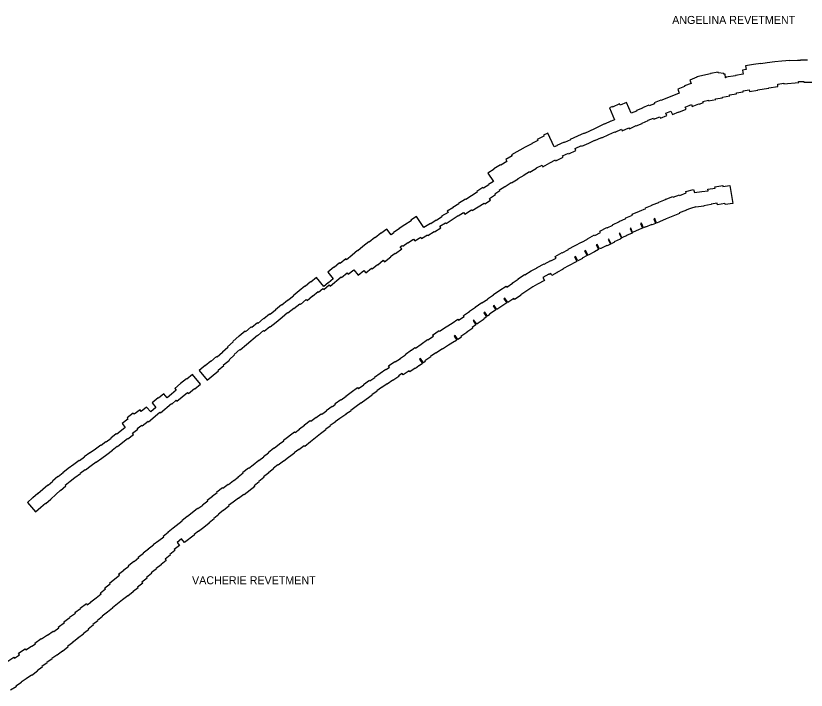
# Model space of a CAD drawing. Extents: x 2650582 to 3923188, y 277893 to 989177.
# Drawn here: x 3479786 to 3495593, y 553438 to 566923 of the extents above; entities that cross this region are included whole.
import ezdxf

# ---------------------------------------------------------------- set-up
doc = ezdxf.new("R2010")
doc.units = 0
doc.layers.add('Level 3', color=7, linetype='Continuous')

msp = doc.modelspace()

# ---------------------------------------------------------------- linework, layer by layer
at = {"layer": 'Level 3'}
for points in [[(3495619, 566037), (3495479, 566039), (3495479, 566026), (3495417, 566027), (3495417, 566031), (3495267, 566023), (3495267, 566030), (3495108, 566015), (3495108, 566018), (3494968, 566000), (3494968, 566004), (3494814, 565984), (3494814, 565982), (3494684, 565962), (3494683, 565967), (3494538, 565949), (3494538, 565952), (3494380, 565925), (3494393, 565848), (3494318, 565835), (3494331, 565754), (3494180, 565728), (3494180, 565724), (3493988, 565694), (3493989, 565685), (3493982, 565684), (3493970, 565758), (3493945, 565754), (3493947, 565770), (3493835, 565785), (3493834, 565793), (3493679, 565769), (3493680, 565761), (3493403, 565704), (3493405, 565693), (3493264, 565639), (3493290, 565571), (3493156, 565520), (3493160, 565508), (3493023, 565455), (3493055, 565374), (3492808, 565273), (3492807, 565275), (3492688, 565231), (3492686, 565235), (3492555, 565183), (3492562, 565163), (3492454, 565122), (3492449, 565133), (3492318, 565080)], [(3492195, 564721), (3492315, 564771), (3492312, 564779), (3492433, 564828), (3492432, 564833), (3492538, 564877), (3492549, 564853), (3492664, 564901), (3492676, 564875), (3492809, 564929), (3492789, 564979), (3492887, 565019), (3492916, 564949), (3493044, 565000), (3493046, 564994), (3493192, 565053), (3493175, 565099), (3493297, 565149), (3493313, 565109), (3493449, 565161), (3493450, 565158), (3493537, 565192), (3493529, 565212), (3493636, 565238), (3493640, 565221), (3493784, 565249), (3493782, 565263), (3493920, 565285), (3493918, 565299), (3494063, 565321), (3494059, 565342), (3494198, 565361), (3494197, 565381), (3494333, 565401), (3494331, 565425), (3494454, 565441), (3494460, 565408), (3494623, 565436), (3494622, 565441), (3494845, 565474), (3494845, 565483), (3495029, 565506), (3495024, 565558), (3495146, 565574), (3495148, 565561), (3495443, 565587), (3495442, 565608), (3495548, 565610), (3495549, 565597), (3495704, 565594)], [(3492095, 564975), (3492001, 565192), (3491870, 565135), (3491859, 565160), (3491721, 565098), (3491717, 565107), (3491658, 565081), (3491761, 564846), (3491690, 564814), (3491689, 564817), (3491559, 564756), (3491557, 564760), (3491358, 564666), (3491359, 564663), (3491156, 564572), (3491155, 564575), (3491022, 564515), (3491020, 564519), (3490875, 564451), (3490879, 564443), (3490758, 564389), (3490755, 564395), (3490604, 564327), (3490606, 564324), (3490552, 564301), (3490423, 564574), (3490338, 564534), (3490347, 564516), (3490214, 564452), (3490223, 564431), (3490103, 564372), (3490107, 564362), (3489973, 564294), (3489971, 564297), (3489700, 564146), (3489712, 564124), (3489584, 564048), (3489605, 564012), (3489487, 563938), (3489481, 563946), (3489346, 563863), (3489350, 563856), (3489229, 563779), (3489337, 563611), (3489239, 563550), (3489243, 563544), (3489137, 563477), (3489129, 563489), (3489005, 563410), (3489015, 563394), (3488786, 563248), (3488779, 563258), (3488642, 563171), (3488644, 563166), (3488524, 563091), (3488528, 563086), (3488415, 563016), (3488430, 562992), (3488302, 562914), (3488309, 562902), (3488196, 562833), (3488194, 562835), (3488083, 562764), (3488077, 562772), (3487943, 562689), (3487801, 562908), (3487685, 562836), (3487693, 562822), (3487566, 562744), (3487568, 562741), (3487451, 562669), (3487456, 562661), (3487342, 562588), (3487347, 562580), (3487292, 562543)], [(3492318, 565080), (3492320, 565074), (3492199, 565026), (3492202, 565019), (3492095, 564975)], [(3487503, 562263), (3487474, 562302), (3487516, 562330), (3487524, 562319), (3487625, 562389), (3487628, 562384), (3487742, 562458), (3487764, 562422), (3487883, 562495), (3487902, 562467), (3488017, 562543), (3488027, 562528), (3488150, 562609), (3488156, 562600), (3488286, 562683), (3488268, 562715), (3488381, 562785), (3488392, 562769), (3488631, 562927), (3488635, 562920), (3488741, 562989), (3488764, 562954), (3488900, 563045), (3488912, 563027), (3489150, 563179), (3489163, 563160), (3489280, 563236), (3489259, 563271), (3489377, 563347), (3489365, 563366), (3489466, 563432), (3489460, 563442), (3489569, 563512), (3489572, 563508), (3489695, 563588), (3489698, 563582), (3489834, 563665), (3489833, 563667), (3489955, 563739), (3489953, 563744), (3490062, 563807), (3490067, 563799), (3490202, 563876), (3490200, 563880), (3490311, 563938), (3490328, 563905), (3490469, 563980), (3490467, 563986), (3490578, 564042), (3490589, 564022), (3490732, 564094), (3490720, 564120), (3490840, 564174), (3490845, 564164), (3490988, 564230), (3490971, 564270), (3491100, 564328), (3491105, 564315), (3491244, 564375), (3491243, 564379), (3491366, 564433), (3491368, 564428), (3491500, 564490), (3491505, 564480), (3491649, 564547), (3491647, 564552), (3491766, 564605), (3491770, 564596), (3491900, 564655), (3491914, 564625), (3492049, 564683), (3492056, 564666), (3492192, 564727), (3492195, 564721)], [(3490711, 562187), (3490712, 562185), (3490836, 562253), (3490834, 562256), (3490973, 562333), (3490975, 562328), (3491102, 562398), (3491104, 562394), (3491221, 562459), (3491218, 562465), (3491359, 562540), (3491364, 562531), (3491477, 562591), (3491465, 562614), (3491608, 562687), (3491611, 562683), (3491726, 562738), (3491722, 562744), (3491856, 562808), (3491855, 562812), (3491988, 562870), (3491984, 562880), (3492121, 562937), (3492114, 562955), (3492262, 563016), (3492262, 563016), (3492385, 563067), (3492378, 563083), (3492514, 563137), (3492513, 563140), (3492647, 563193), (3492646, 563195), (3492777, 563247), (3492775, 563251), (3492924, 563310), (3492931, 563294), (3493061, 563345), (3493067, 563330), (3493195, 563380), (3493188, 563409), (3493341, 563450), (3493357, 563390), (3493504, 563411), (3493505, 563407), (3493632, 563425), (3493627, 563458), (3493773, 563478), (3493769, 563505), (3493926, 563528), (3493929, 563508), (3494069, 563532), (3494129, 563173)], [(3494129, 563173), (3493973, 563147), (3493969, 563167), (3493819, 563145), (3493815, 563174), (3493690, 563157), (3493691, 563147), (3493544, 563126), (3493546, 563117), (3493389, 563095), (3493388, 563100), (3493278, 563071), (3493278, 563073), (3493183, 563035), (3493185, 563032), (3493054, 562981), (3493058, 562971), (3492927, 562919), (3492929, 562915), (3492794, 562862), (3492795, 562860), (3492660, 562806), (3492661, 562803), (3492599, 562779), (3492563, 562868), (3492546, 562862), (3492582, 562772), (3492512, 562744), (3492509, 562751), (3492382, 562698), (3492380, 562701), (3492337, 562683), (3492299, 562775), (3492278, 562767), (3492316, 562675), (3492254, 562649), (3492254, 562649), (3492119, 562593), (3492086, 562674), (3492072, 562669), (3492110, 562578), (3492002, 562531), (3492004, 562528), (3491909, 562482), (3491866, 562574), (3491854, 562568), (3491897, 562477), (3491871, 562464), (3491874, 562458), (3491754, 562401), (3491756, 562398), (3491693, 562366), (3491646, 562457), (3491630, 562449), (3491677, 562357), (3491613, 562325), (3491609, 562333), (3491484, 562267), (3491482, 562272), (3491460, 562261), (3491412, 562351), (3491394, 562341), (3491442, 562251), (3491356, 562205), (3491356, 562206), (3491230, 562136), (3491226, 562142), (3491177, 562230), (3491162, 562222), (3491211, 562133), (3491113, 562079), (3491117, 562073), (3491026, 562023), (3490978, 562111), (3490960, 562101), (3491009, 562013), (3490978, 561997), (3490977, 561999)], [(3487292, 562543), (3487206, 562657), (3487089, 562568), (3487084, 562575), (3486972, 562486), (3486968, 562489), (3486856, 562397), (3486848, 562406), (3486728, 562307), (3486727, 562308), (3486626, 562225), (3486622, 562229), (3486512, 562136), (3486510, 562139), (3486398, 562045), (3486384, 562062), (3486272, 561972), (3486262, 561983), (3486152, 561893), (3486149, 561896), (3486028, 561797), (3486136, 561664), (3486038, 561584), (3486036, 561586), (3485948, 561513), (3485798, 561692), (3485687, 561600), (3485682, 561606), (3485572, 561513), (3485569, 561516), (3485453, 561422), (3485452, 561423), (3485332, 561322), (3485337, 561317), (3485225, 561227), (3485220, 561232), (3485104, 561138), (3485098, 561145), (3484977, 561045)], [(3484618, 560539), (3484625, 560530), (3484741, 560628), (3484753, 560614), (3484867, 560712), (3484875, 560702), (3484990, 560799), (3484994, 560794), (3485112, 560894), (3485110, 560896), (3485221, 560989), (3485228, 560981), (3485344, 561077), (3485349, 561071), (3485463, 561166), (3485477, 561150), (3485592, 561249), (3485610, 561228), (3485717, 561321), (3485721, 561316), (3485832, 561409), (3485842, 561397), (3485929, 561469), (3485947, 561448), (3486054, 561541), (3486076, 561516), (3486292, 561702), (3486301, 561693), (3486412, 561783), (3486436, 561754), (3486545, 561845), (3486636, 561736), (3486748, 561829), (3486788, 561781), (3486901, 561874), (3486911, 561862), (3487019, 561949), (3487023, 561945), (3487132, 562038), (3487160, 562004), (3487284, 562104), (3487282, 562107), (3487370, 562179), (3487377, 562169), (3487503, 562263)], [(3487237, 559927), (3487367, 560013), (3487375, 560001), (3487481, 560072), (3487480, 560074), (3487579, 560143), (3487574, 560150), (3487699, 560242), (3487700, 560240), (3487769, 560291), (3487779, 560279), (3487891, 560359), (3487891, 560359), (3488018, 560450), (3488023, 560442), (3488136, 560520), (3488122, 560540), (3488251, 560630), (3488259, 560619), (3488390, 560704), (3488392, 560701), (3488512, 560780), (3488514, 560777), (3488629, 560855), (3488640, 560839), (3488750, 560913), (3488740, 560927), (3488861, 561009), (3488856, 561016), (3488976, 561097), (3488974, 561100), (3489105, 561188), (3489109, 561182), (3489224, 561259), (3489221, 561263), (3489341, 561344), (3489338, 561349), (3489468, 561436), (3489469, 561434), (3489593, 561518), (3489606, 561499), (3489716, 561574), (3489714, 561576), (3489833, 561656), (3489830, 561661), (3489962, 561748), (3489963, 561746), (3490093, 561824), (3490094, 561823), (3490213, 561886), (3490212, 561889), (3490351, 561963), (3490354, 561958), (3490484, 562027), (3490486, 562023), (3490591, 562078), (3490573, 562111), (3490711, 562187)], [(3490977, 561999), (3490853, 561930), (3490853, 561930), (3490729, 561861), (3490731, 561858), (3490608, 561793), (3490610, 561788), (3490505, 561732), (3490485, 561770), (3490451, 561752), (3490448, 561757), (3490325, 561692), (3490358, 561629), (3490218, 561555), (3490216, 561560), (3490123, 561504), (3490124, 561502), (3490007, 561425), (3490008, 561423), (3489888, 561342), (3489890, 561339), (3489759, 561251), (3489746, 561269), (3489625, 561188), (3489566, 561276), (3489548, 561264), (3489604, 561181), (3489407, 561048), (3489350, 561132), (3489334, 561121), (3489388, 561041), (3489262, 560956), (3489267, 560948), (3489220, 560915), (3489164, 560998), (3489147, 560986), (3489202, 560904), (3489147, 560866), (3489151, 560860), (3489031, 560778), (3489033, 560774), (3489004, 560754), (3488947, 560838), (3488932, 560828), (3488989, 560744), (3488914, 560693), (3488924, 560679), (3488803, 560598), (3488806, 560592), (3488686, 560511), (3488697, 560495), (3488626, 560449), (3488573, 560531), (3488555, 560520), (3488608, 560437), (3488565, 560409), (3488562, 560413), (3488442, 560335), (3488438, 560340), (3488320, 560257), (3488316, 560263), (3488189, 560176), (3488184, 560183), (3488081, 560109), (3488085, 560104), (3487969, 560021), (3487975, 560013), (3487938, 559986), (3487877, 560069), (3487860, 560056), (3487921, 559973), (3487850, 559921), (3487849, 559922), (3487780, 559871), (3487774, 559879), (3487667, 559805), (3487653, 559824), (3487531, 559741), (3487512, 559769), (3487441, 559723)], [(3484977, 561045), (3484980, 561040), (3484871, 560948), (3484861, 560960), (3484746, 560862), (3484741, 560869), (3484626, 560773), (3484617, 560783), (3484506, 560691), (3484496, 560702), (3484380, 560606), (3484372, 560615), (3484255, 560518), (3484252, 560521), (3484126, 560413), (3484136, 560401), (3484019, 560303), (3484029, 560291), (3483918, 560194), (3483922, 560190), (3483812, 560097), (3483801, 560109), (3483687, 560013), (3483683, 560017), (3483575, 559926), (3483571, 559930), (3483452, 559828)], [(3483452, 559828), (3483615, 559634), (3483734, 559734), (3483733, 559735), (3483842, 559825), (3483832, 559838), (3483948, 559932), (3483939, 559943), (3484057, 560040), (3484052, 560046), (3484162, 560142), (3484154, 560152), (3484268, 560249), (3484274, 560242), (3484400, 560348), (3484397, 560350), (3484618, 560539)], [(3486637, 559464), (3486641, 559467), (3486639, 559471), (3486744, 559545), (3486740, 559550), (3486861, 559634), (3486869, 559623), (3486963, 559689), (3486958, 559697), (3487185, 559856), (3487190, 559850), (3487257, 559897), (3487237, 559927)], [(3483480, 559558), (3483319, 559751), (3483204, 559658), (3483198, 559666), (3483082, 559568), (3483081, 559569), (3482963, 559469), (3482990, 559435), (3482899, 559359), (3482901, 559356), (3482812, 559282), (3482744, 559363), (3482640, 559277), (3482636, 559282), (3482516, 559181), (3482589, 559093), (3482483, 559002), (3482399, 559099), (3482295, 559013), (3482272, 559043), (3482155, 558955), (3482135, 558979), (3482011, 558882), (3482028, 558859), (3481912, 558770)], [(3487441, 559723), (3487448, 559713), (3487327, 559628), (3487323, 559635), (3487213, 559558), (3487210, 559563), (3487104, 559488), (3487101, 559493), (3487006, 559427), (3487012, 559418), (3486906, 559344), (3486913, 559334), (3486793, 559250), (3486793, 559251), (3486692, 559180), (3486692, 559181), (3486592, 559111), (3486595, 559108), (3486487, 559032), (3486490, 559027), (3486385, 558954), (3486387, 558952), (3486267, 558868), (3486265, 558869), (3486170, 558803), (3486173, 558798), (3486076, 558730), (3486080, 558724), (3485981, 558649), (3485983, 558647), (3485878, 558567), (3485880, 558564), (3485777, 558486), (3485781, 558482), (3485680, 558405), (3485682, 558402), (3485565, 558313), (3485555, 558327), (3485448, 558245), (3485444, 558252), (3485353, 558183), (3485357, 558178), (3485240, 558089), (3485240, 558090), (3485143, 558016)], [(3482223, 558658), (3482214, 558670), (3482305, 558739), (3482314, 558727), (3482431, 558818), (3482442, 558806), (3482666, 558998), (3482678, 558985), (3482897, 559169), (3482906, 559159), (3482996, 559234), (3483008, 559219), (3483221, 559393), (3483241, 559369), (3483361, 559471), (3483366, 559464), (3483480, 559558)], [(3486182, 559154), (3486173, 559168), (3486289, 559252), (3486293, 559246), (3486391, 559316), (3486388, 559320), (3486494, 559396), (3486493, 559397), (3486620, 559488), (3486637, 559464)], [(3484951, 558279), (3485062, 558364), (3485062, 558363), (3485146, 558427), (3485138, 558437), (3485358, 558605), (3485370, 558590), (3485461, 558659), (3485459, 558662), (3485562, 558740), (3485558, 558744), (3485675, 558833), (3485688, 558817), (3485792, 558897), (3485796, 558891), (3485895, 558967), (3485905, 558954), (3486001, 559022), (3485993, 559032), (3486113, 559116), (3486118, 559109), (3486182, 559154)], [(3481912, 558770), (3481973, 558690), (3481898, 558632), (3481899, 558631), (3481803, 558556), (3481796, 558565), (3481686, 558479), (3481691, 558472), (3481593, 558396), (3481587, 558404), (3481490, 558328), (3481485, 558335), (3481379, 558258), (3481377, 558259), (3481271, 558181), (3481266, 558187), (3481153, 558105), (3481157, 558099), (3481057, 558026), (3481054, 558030), (3480947, 557953), (3480946, 557954), (3480833, 557872), (3480834, 557870), (3480728, 557787), (3480730, 557784), (3480630, 557706), (3480628, 557708), (3480522, 557616), (3480524, 557614), (3480431, 557533), (3480427, 557537), (3480228, 557363), (3480224, 557368), (3480124, 557282), (3480122, 557284), (3480017, 557192)], [(3480017, 557192), (3480180, 557004), (3480286, 557096), (3480284, 557098), (3480378, 557179), (3480383, 557173), (3480483, 557257), (3480589, 557350), (3480586, 557354), (3480679, 557436), (3480682, 557433), (3480787, 557524), (3480775, 557539), (3480872, 557615), (3480871, 557617), (3480965, 557690), (3480966, 557689), (3481079, 557771), (3481074, 557778), (3481175, 557850), (3481178, 557845), (3481292, 557928), (3481291, 557929), (3481391, 558001), (3481396, 557995), (3481509, 558078), (3481507, 558080), (3481606, 558151), (3481607, 558150), (3481717, 558236), (3481715, 558240), (3481813, 558316), (3481817, 558311), (3481927, 558397), (3481925, 558399), (3482021, 558474), (3482027, 558467), (3482137, 558553), (3482119, 558577), (3482223, 558658)], [(3482040, 555931), (3482149, 556016), (3482151, 556014), (3482245, 556088), (3482235, 556101), (3482337, 556179), (3482334, 556182), (3482438, 556263), (3482435, 556267), (3482537, 556346), (3482536, 556348), (3482646, 556433), (3482648, 556431), (3482744, 556506), (3482733, 556520), (3482834, 556598), (3482830, 556602), (3482932, 556682), (3482930, 556685), (3483112, 556827), (3483106, 556834), (3483216, 556920), (3483218, 556917), (3483313, 556991), (3483312, 556992), (3483422, 557078), (3483429, 557069), (3483523, 557141), (3483520, 557145), (3483624, 557226), (3483616, 557237), (3483717, 557316), (3483716, 557317), (3483816, 557394), (3483809, 557403), (3483920, 557488), (3483929, 557476), (3484034, 557557), (3484037, 557553), (3484142, 557634), (3484145, 557630), (3484234, 557699), (3484230, 557705), (3484332, 557784), (3484323, 557796), (3484438, 557886), (3484446, 557876), (3484533, 557943), (3484531, 557946), (3484647, 558035), (3484649, 558032), (3484744, 558105), (3484742, 558109), (3484841, 558185), (3484834, 558194), (3484948, 558283), (3484951, 558279)], [(3485143, 558016), (3485139, 558020), (3485033, 557938), (3485028, 557945), (3484942, 557878), (3484949, 557870), (3484840, 557786), (3484843, 557782), (3484741, 557703), (3484749, 557692), (3484649, 557614), (3484656, 557605), (3484553, 557525), (3484566, 557509), (3484351, 557342), (3484345, 557350), (3484242, 557271), (3484237, 557278), (3484133, 557197), (3484130, 557201), (3484038, 557129), (3484048, 557117), (3483937, 557032), (3483936, 557033), (3483840, 556959), (3483846, 556952), (3483745, 556873), (3483752, 556864), (3483650, 556784), (3483654, 556779), (3483544, 556693), (3483544, 556693), (3483441, 556614), (3483439, 556616), (3483350, 556548), (3483356, 556540), (3483161, 556388), (3483102, 556463), (3483010, 556391), (3483057, 556329), (3482953, 556248), (3482966, 556230), (3482865, 556151), (3482876, 556138), (3482774, 556059), (3482795, 556032), (3482690, 555951), (3482693, 555947), (3482592, 555869), (3482597, 555862), (3482494, 555782), (3482500, 555773), (3482399, 555694), (3482411, 555679), (3482307, 555599)], [(3481216, 555145), (3481287, 555201), (3481286, 555202), (3481391, 555283), (3481390, 555284), (3481493, 555364), (3481477, 555384), (3481581, 555465), (3481566, 555483), (3481670, 555564), (3481657, 555581), (3481765, 555665), (3481766, 555664), (3481860, 555737), (3481842, 555760), (3481945, 555840), (3481944, 555842), (3482047, 555921), (3482040, 555931)], [(3482307, 555599), (3482323, 555578), (3482220, 555498), (3482230, 555486), (3482130, 555409), (3482133, 555405), (3482024, 555321), (3482024, 555322), (3481920, 555242), (3481919, 555243), (3481819, 555166), (3481822, 555162), (3481720, 555083), (3481722, 555080), (3481618, 554999), (3481619, 554998), (3481516, 554918), (3481520, 554914), (3481417, 554834), (3481424, 554826), (3481324, 554749), (3481335, 554735), (3481230, 554656), (3481239, 554645), (3481135, 554567), (3481139, 554561), (3481029, 554478), (3481031, 554476), (3480922, 554394), (3480924, 554391), (3480820, 554311), (3480829, 554299), (3480719, 554214), (3480718, 554216), (3480612, 554136), (3480608, 554141), (3480508, 554069), (3480512, 554064), (3480408, 553990), (3480410, 553987), (3480304, 553912), (3480314, 553897), (3480216, 553827), (3480222, 553819), (3480103, 553733), (3480101, 553736), (3479995, 553662), (3479991, 553667), (3479893, 553600), (3479898, 553593), (3479786, 553518), (3479793, 553507), (3479681, 553438)], [(3480634, 554697), (3480760, 554789), (3480747, 554807), (3480864, 554891), (3480861, 554896), (3480980, 554975), (3480967, 554994), (3481079, 555069), (3481071, 555081), (3481199, 555169), (3481216, 555145)], [(3479491, 553940), (3479486, 553947), (3479617, 554034), (3479627, 554019), (3479745, 554096), (3479757, 554079), (3479860, 554147), (3479841, 554176), (3479975, 554263), (3479987, 554246), (3480101, 554321), (3480104, 554317), (3480178, 554366), (3480168, 554380), (3480296, 554470), (3480301, 554463), (3480419, 554545), (3480422, 554540), (3480536, 554621), (3480544, 554610), (3480645, 554682), (3480634, 554697)]]:
    msp.add_lwpolyline(points, dxfattribs=at)

# ---------------------------------------------------------------- texts
for s, p in [('ANGELINA REVETMENT', (3492913, 566760)), ('VACHERIE REVETMENT', (3483310, 555556))]:
    msp.add_text(s, height=160, dxfattribs=at).set_placement(p)

doc.saveas('drawing.dxf')
